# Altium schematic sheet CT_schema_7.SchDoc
size 308 x 210 mm
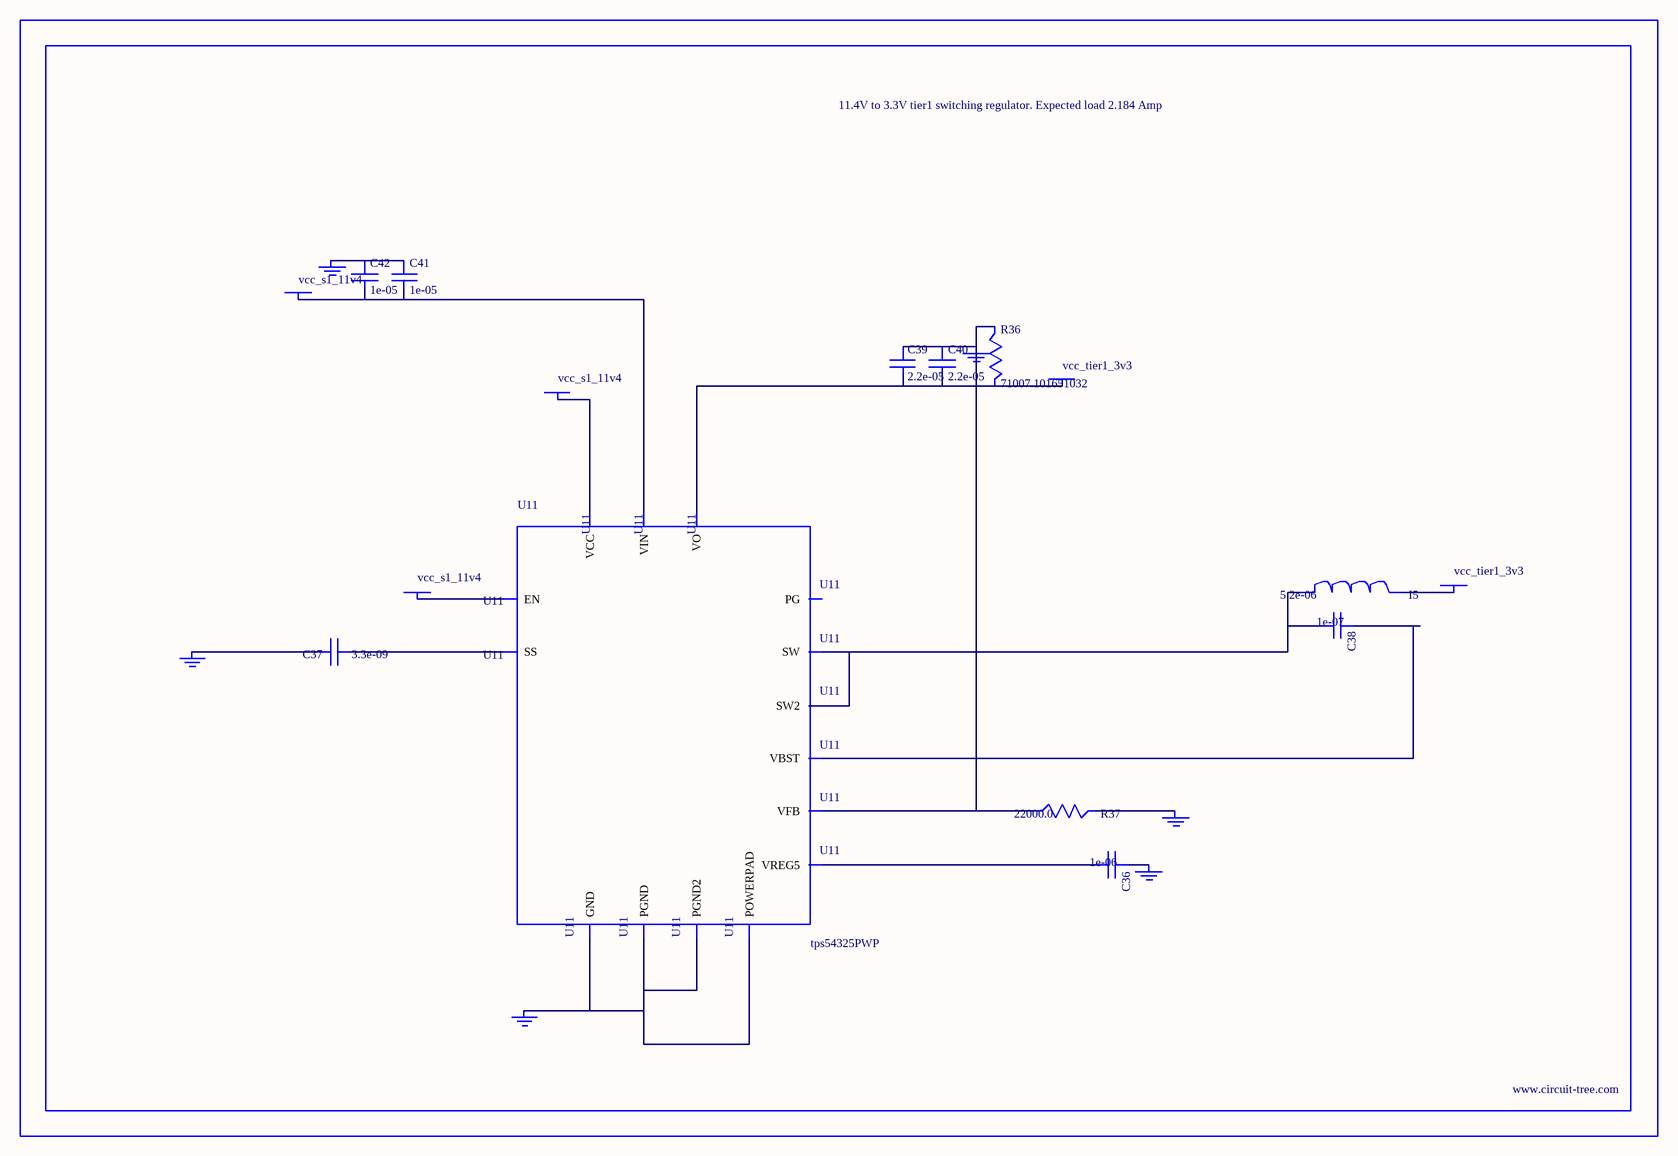
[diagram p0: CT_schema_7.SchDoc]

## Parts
BORDER6  (no value)
C36  1e-06  [C0603]
C37  3.3e-09  [C0402]
C38  1e-07  [C0402]
C39  2.2e-05  [C1210]
C40  2.2e-05  [C1210]
C41  1e-05  [C1206]
C42  1e-05  [C1206]
GND_INSTANCE_6_0  (no value)
GND_INSTANCE_6_1  (no value)
GND_INSTANCE_6_2  (no value)
GND_INSTANCE_6_3  (no value)
GND_INSTANCE_6_4  (no value)
GND_INSTANCE_6_5  (no value)
I5  5.2e-06  [DR1040]
POWER_INSTANCE_6_0  vcc_tier1_3v3
POWER_INSTANCE_6_1  vcc_s1_11v4
POWER_INSTANCE_6_2  vcc_tier1_3v3
POWER_INSTANCE_6_3  vcc_s1_11v4
POWER_INSTANCE_6_4  vcc_s1_11v4
R36  71007.101651032  [R0603]
R37  22000.0  [R0603]
U11  tps54325PWP  [HTSSOP14]

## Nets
NetC36_1: C36.1 GND_INSTANCE_6_2.0(GND)
NetC36_2: C36.2 U11.3(VREG5)
NetC37_1: C37.1 U11.4(SS)
NetC37_2: C37.2 GND_INSTANCE_6_3.0(GND)
NetC38_1: C38.1 U11.12(VBST)
NetC38_2: C38.2 I5.1 U11.10(SW) U11.11(SW2)
NetC39_1: C39.1 C40.1 GND_INSTANCE_6_0.0(GND) R36.1 R37.1 U11.2(VFB)
NetC39_2: C39.2 C40.2 POWER_INSTANCE_6_0.0(PWR) R36.2 U11.1(VO)
NetC41_1: C41.1 C42.1 GND_INSTANCE_6_5.0(GND)
NetC41_2: C41.2 C42.2 POWER_INSTANCE_6_3.0(PWR) U11.13(VIN)
NetGND_INSTANCE_6_1_0: GND_INSTANCE_6_1.0(GND) R37.2
NetGND_INSTANCE_6_4_0: GND_INSTANCE_6_4.0(GND) U11.5(GND) U11.8(PGND) U11.9(PGND2) U11.15(POWERPAD)
NetI5_2: I5.2 POWER_INSTANCE_6_2.0(PWR)
NetPOWER_INSTANCE_6_1_0: POWER_INSTANCE_6_1.0(PWR) U11.7(EN)
NetPOWER_INSTANCE_6_4_0: POWER_INSTANCE_6_4.0(PWR) U11.14(VCC)

Not connected (* = marked no-connect by the designer): U11 6(PG)

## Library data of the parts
BORDER6 = BORDER_PAGE6
C36 = C0603C105K3RACTU
C37 = C0402C332K3RAC
C38 = C0402C104K3RACTU
C39 C40 = GRM32ER61E226ME15L
C41 C42 = C1206C106K3RACTU
GND_INSTANCE_6_0-GND_INSTANCE_6_5 = GND
I5 = DR1040-5R2-R
POWER_INSTANCE_6_0-POWER_INSTANCE_6_4 = PWR
R36 = R36
R37 = RC0603JR-0722KL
